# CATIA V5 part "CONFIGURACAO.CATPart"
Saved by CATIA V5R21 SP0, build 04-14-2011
Part number: Part1
Bounding box of the stored display mesh (mm): x -150 to 150, y -548.912 to 550, z 0 to 200
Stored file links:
  C:\Users\rodri\OneDrive\Área de Trabalho\FACULDADE\3°semestre\Sistemas Aeroespaciais\Projeto de avião 2019-02\CAD\CONFIGURACAO.CATPart
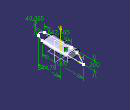
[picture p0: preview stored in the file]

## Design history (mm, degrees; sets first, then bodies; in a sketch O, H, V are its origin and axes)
Body1 (main body)
  Sketch1 on yz-plane, origin (0, 0, 0), H (0, 1, 0), V (0, 0, 1)
    point P1 (-300, 160)
    line L1 (-300, 160) -> (-300, 10)
    arc A1 centre (0, 4505) radius 4505 from (-300, 10) to (300, 10) ccw
    line L2 (300, 10) -> (300, 160)
    arc A2 centre (0, 4655) radius 4505 from (300, 160) to (-300, 160) cw
    point P7 (0, 150)
    length L1 = 150
    length L2 = 150
    distance L1 L2 = 600
    distance A2 A1 = 150
    distance P1 H = 160
    vertical: L1 V, L2 V
    coincidence: A1 O, A2 P7, P7 V
    symmetry: L2 L1 V
    tangency: A1 H
  Pad1: profile Sketch1, direction (1, 0, 0), length 150, mirrored extent
  Sketch2 on face of Pad1 from Sketch1.L1, origin (0, -300, 0), H (1, 0, 0), V (0, 0, 1)
    point P1 (0, 85)
    ellipse A1 centre (0, 85) semi-axes 150, 75 rotation 0
    reference projected line E1 (-150, 10) -> (150, 10) from edge [face of Pad1 from Sketch1.A1 | face of Pad1 from Sketch1.L1]
    line L1 (-315.5085, 248.0164) -> (304.8358, 248.0164)
    line L2 (304.8358, 248.0164) -> (304.8358, -127.6508)
    line L3 (304.8358, -127.6508) -> (-315.5085, -127.6508)
    line L4 (-315.5085, -127.6508) -> (-315.5085, 248.0164)
    "Radius" A1 = 150
    distance P1 E1 = 75
    "Radius" A1 = 75
  Sketch3 on yz-plane, origin (0, 0, 0), H (0, 1, 0), V (0, 0, 1)
    arc A1 centre (0, 4655) radius 4580 from (-559.7604, 109.3352) to (519.2883, 104.5341) ccw
    reference projected arc E1 centre (0, 4655) radius 4505 from (-300, 160) to (300, 160) ccw from Sketch1.A2
    reference projected arc E2 centre (0, 4505) radius 4505 from (-300, 10) to (300, 10) ccw from Sketch1.A1
    reference projected arc E3 centre (0, 4655) radius 4505 from (-300, 160) to (300, 160) ccw from Sketch1.A2
    distance A1 E1 = 75
    distance A1 E2 = 75
    radius E3 = 4505 (reference)
    radius A1 = 4580
  Slot1: profile Sketch2, centre curve Sketch3
  Sketch4 on yz-plane, origin (0, 0, 0), H (0, 1, 0), V (0, 0, 1)
    point P1 (550, 0)
    line L1 (550, 0) -> (-450, 0)
    point P2 (-450, 0)
    point P3 (-391.6076, 200)
    line L2 (-391.6076, 200) -> (250.9574, 200)
    point P4 (250.9574, 200)
    spline S1 through (250.9574, 200) (388.5689, 159.935) (550, 0)
    axis line L3 (-343.8801, 159.935) -> (453.8532, 159.935)
    reference projected line E1 (300, 160) -> (300, 10) from edge [face of Slot1 | face of Pad1 from Sketch1.L2]
    spline S2 through (-450, 0) (-544.7902, 60.5912) (-391.6076, 200)
    point P7 (250.9574, 200)
    point P8 (550, 0)
    point P9 (-450, 0)
    point P10 (-391.6076, 200)
    point P11 (-544.7902, 60.5912)
    length L1 = 1000
    distance L2 L1 = 200
    distance L2 L3 = 40.065
    distance P8 E1 = 250
    length L2 = 642.565
    distance P11 V = 544.7902
    horizontal: L1 H, L2 H, L3 H
    coincidence: P7 P4, P1 P8, P9 P2, P10 P3
  Pad2: profile Sketch4, direction (1, 0, 0), length 250, mirrored extent
  Fillet1: radius 60, on edge [start face of Pad2 | face of Pad2 from Sketch4.L1]
  Fillet2: radius 60, on edge [face of Pad2 from Sketch4.L1 | end face of Pad2]
  Sketch5 on face of Pad2 from Sketch4.L1, origin (0, 0, 0), H (1, 0, 0), V (0, -1, 0)
    point P1 (175, -250)
    line L1 (175, -250) -> (441.9906, -250)
    line L2 (441.9906, -250) -> (441.9906, -750)
    line L3 (441.9906, -750) -> (175, -750)
    line L4 (175, -750) -> (175, -250)
    point P2 (441.9906, -250)
    point P3 (441.9906, -750)
    point P4 (175, -750)
    reference projected line E1 (250, 544.4967) -> (250, -509.1971) from edge [face of Fillet2 | end face of Pad2]
    point P5 (-441.9906, -250)
    point P6 (-175, -250)
    line L5 (-175, -250) -> (-441.9906, -250)
    point P7 (-175, -750)
    line L6 (-175, -750) -> (-175, -250)
    point P8 (-441.9906, -750)
    line L7 (-441.9906, -250) -> (-441.9906, -750)
    line L8 (-441.9906, -750) -> (-175, -750)
    distance H L1 = 250
    distance E1 L4 = 75
    length L2 = 500
    horizontal: L1 H, L3 H
    vertical: L2 V, L4 V
    symmetry: P2 P5 V, P1 P6 V, L1 L5 V, P4 P7 V, L4 L6 V, P3 P8 V, L2 L7 V, L3 L8 V
  Pocket1: profile Sketch5, direction (0, 0, 1), through (limit type 3)
  Fillet3: radius 60, on edge [face of Pocket1 from Sketch5.L4 | face of Pocket1 from Sketch5.L1]
  Fillet4: radius 60, on edge [face of Pocket1 from Sketch5.L5 | face of Pocket1 from Sketch5.L6]
  Fillet5: radius 25, on edge [face of Pad2 from Sketch4.L2 | end face of Pad2]
  Fillet6: radius 30, on edge [face of Pad2 from Sketch4.S1 | face of Pad2 from Sketch4.L2]
  Fillet7: radius 25, on edge [start face of Pad2 | face of Pad2 from Sketch4.L2]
